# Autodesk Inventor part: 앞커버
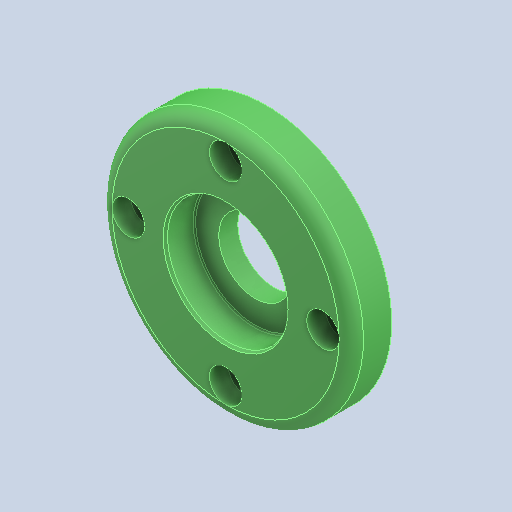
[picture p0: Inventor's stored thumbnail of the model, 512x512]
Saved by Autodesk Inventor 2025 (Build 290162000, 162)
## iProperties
Created: 2025-08
Part Number: 앞커버
Material: 알루미늄 6061
Document SubType Name: Modeling
Designer: infra028
Density: 2.71 g/cm^3
Appearance: 기본값
Author: jhkim
Sending System: Autodesk Inventor 2026
Preprocessor: ST-DEVELOPER v20.1
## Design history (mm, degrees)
feature "솔리드1"
node "솔리드2"
